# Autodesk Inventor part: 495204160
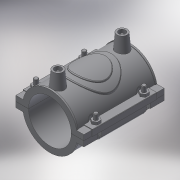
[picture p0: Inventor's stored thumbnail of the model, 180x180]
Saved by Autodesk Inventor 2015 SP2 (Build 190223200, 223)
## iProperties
Created: 2017-07
Part Number: 495204160
Material: Generic
Description: PLASSON REPAIR SADDLE 160
Document SubType Name: Modeling
Designer: KIM
Density: 1 g/cm^3
Appearance: Default
Author: KIM
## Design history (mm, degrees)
derived "495204.ipt"
feature "Solid1::495204.ipt"
tag "TaggingFeature1"
body "Solid1"
other parameters: "d1" = 185.6, "d2" = 199, "d4" = 118, "d5" = 0, "d6" = 0.1, "d8" = 0, "d19" = 6, "d20" = 6, "d21" = 70.8, "d23" = 0, "d24" = 35.4, "d26" = 0, "d27" = 3, "d28" = 3, "d29" = 3, "d30" = 53.33333, "d31" = 6, "d32" = 0, "d33" = 0, "d34" = 0.6, "d40" = 96.512, "d41" = 64.9, "d43" = 0, "d45" = 0, "d47" = 100.224, "d48" = 47.2, "d50" = 0, "d70" = 15, "d72" = 0, "d73" = 6, "d75" = 5, "d76" = 0, "d77" = 8, "d78" = 109, "d79" = 15, "d80" = 47.2, "d82" = 5 deg, "d84" = 4, "d85" = 14, "d86" = 0, "d87" = 3, "d88" = 0, "d89" = 1, "d90" = 1, "d91" = 94.4, "d92" = 0, "d93" = 0.5, "d94" = 84.21053, "d96" = 189.312, "d97" = 2.36, "d98" = 0, "d99" = 47.2, "d100" = 0, "d102" = 3.54, "B_" = 199, "H_" = 29, "L_" = 118, "d_t" = 6
